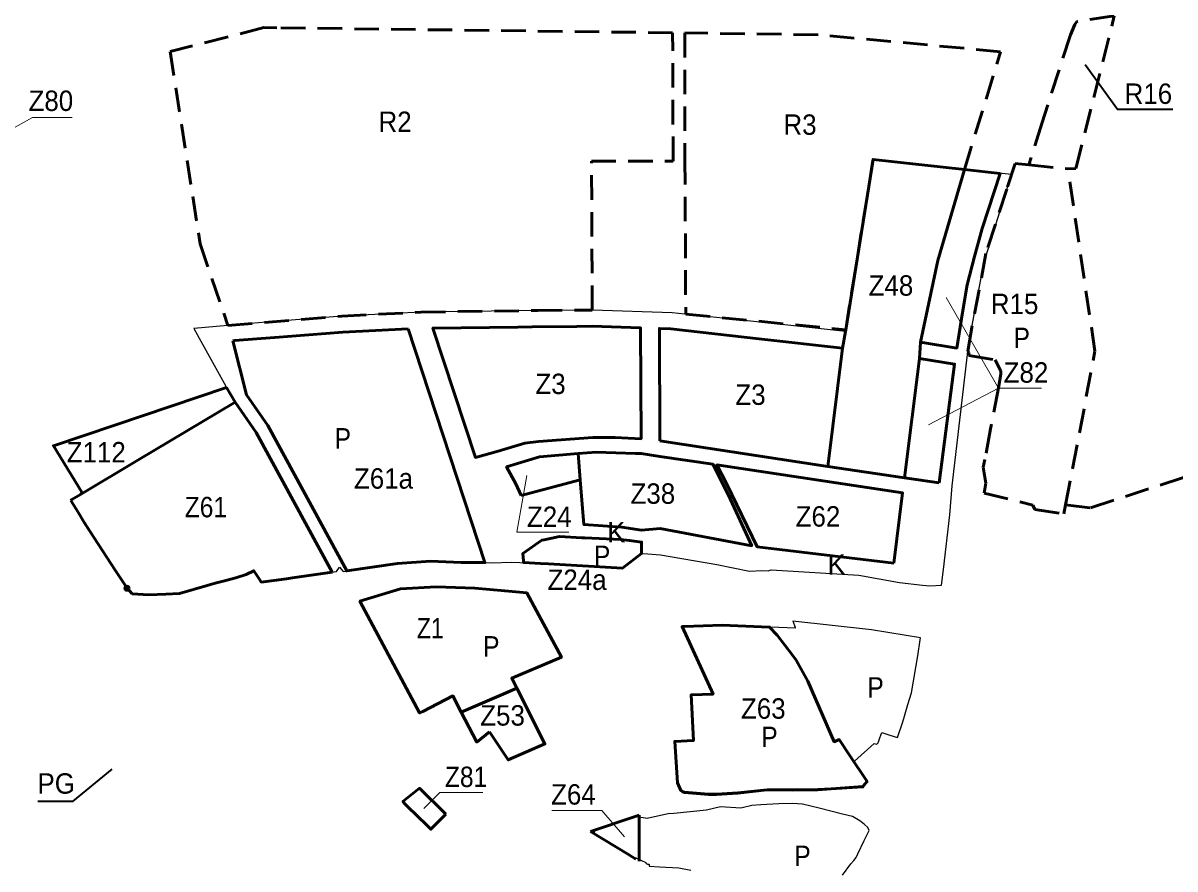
# Model space of a CAD drawing. Extents: x -650246 to -642674, y -1074280 to -1066767.
# Drawn here: x -647810 to -646455, y -1070187 to -1069193 of the extents above; entities that cross this region are included whole.
import ezdxf

# ---------------------------------------------------------------- set-up
doc = ezdxf.new("R2010")
doc.units = 0
doc.header["$LTSCALE"] = 9.6
doc.header["$PDMODE"] = 32
doc.header["$PDSIZE"] = 4.8
doc.linetypes.add('MEDIUM_DASHED', pattern=[4.5, 3, -1.5])
for name, color, linetype, lineweight in [('42', 7, 'Continuous', 25), ('44', 7, 'Continuous', 53), ('45', 7, 'Continuous', 53), ('46', 7, 'Continuous', 13), ('48', 7, 'Continuous', 13), ('60', 7, 'Continuous', 35), ('61', 7, 'MEDIUM_DASHED', 53), ('62', 7, 'Continuous', 35)]:
    doc.layers.add(name, color=color, linetype=linetype, lineweight=lineweight)

msp = doc.modelspace()

# ---------------------------------------------------------------- linework, layer by layer
at = {"layer": '42'}
for points in [[(-647235.49, -1069826.51), (-647205.603, -1069827.72), (-647191.66, -1069828.58), (-647201.106, -1069827.997), (-647191.66, -1069828.58), (-647104.741, -1069833.568), (-647082.145, -1069816.321), (-647074.72, -1069816.8), (-647060.029, -1069817.854), (-646993.81, -1069829.12), (-646993.81, -1069829.12), (-646955.45, -1069836.93), (-646940.94, -1069836.34), (-646933.39, -1069836.51), (-646929.67, -1069835.68), (-646826.63, -1069841.84), (-646778.74, -1069850.44), (-646751.8, -1069853.72), (-646743.31, -1069854.26), (-646729.54, -1069853.69), (-646727.09, -1069835.05), (-646719.79, -1069770.87), (-646716.98, -1069736.73), (-646698.96, -1069582.26), (-646698.96, -1069582.26), (-646698.4, -1069578.93), (-646693.58, -1069550.28), (-646679.13, -1069473.51), (-646647.141, -1069370.826), (-646702.425, -1069364.771), (-646809.879, -1069353.002), (-646842.103, -1069553.182), (-646842.441, -1069555.283), (-646910.029, -1069548.006), (-646986.633, -1069539.757), (-647046.325, -1069533.275), (-647140.008, -1069530.068), (-647204.293, -1069530.647), (-647341.697, -1069532.602), (-647434.969, -1069537.141), (-647523.931, -1069544.499), (-647568.792, -1069548.21), (-647608.81, -1069551.868), (-647598.735, -1069570.026), (-647573.15, -1069616.16), (-647570.37, -1069621.18), (-647570.37, -1069621.18), (-647701.61, -1069665.279), (-647774.11, -1069689.64), (-647740.74, -1069744.24), (-647742.36, -1069746.93), (-647752.32, -1069752.95), (-647753.7, -1069753.9), (-647745.84, -1069766.71), (-647687.45, -1069857.15), (-647681.51, -1069863.72), (-647661.79, -1069864.92), (-647641.78, -1069864.26), (-647625.83, -1069863.19), (-647593.07, -1069853.74), (-647572.63, -1069848.63), (-647559.47, -1069844.92), (-647547.12, -1069840.87), (-647538.34, -1069836.68), (-647531.33, -1069847.23), (-647529.5, -1069849.99), (-647492.76, -1069845.02), (-647441.19, -1069837.6), (-647437.46, -1069832.27), (-647433.32, -1069837.33), (-647369.3, -1069828.22), (-647330.46, -1069825.51), (-647294.38, -1069826.88)], [(-647294.38, -1069826.88), (-647270.09, -1069827.02), (-647258.143, -1069827.094), (-647235.49, -1069826.51)], [(-646753.995, -1069915.425), (-646811.935, -1069906.155), (-646904.446, -1069895.991), (-646901.388, -1069902.723), (-646902.06, -1069902.694), (-646901.388, -1069904.174)], [(-646901.388, -1069904.174), (-646987.56, -1069900.52), (-647032.16, -1069902.13), (-647033.853, -1069902.188)], [(-647033.853, -1069902.188), (-646998.06, -1069980.039), (-646998.716, -1069980.064)], [(-646831.912, -1070060.406), (-646808.49, -1070039.689), (-646805.65, -1070040.439), (-646803.87, -1070038.879), (-646803.43, -1070037.629), (-646801.84, -1070033.139), (-646799.45, -1070026.749), (-646790.27, -1070029.749), (-646781.39, -1070032.779), (-646774.86, -1070014.019), (-646772.96, -1070007.579), (-646768.91, -1069993.979), (-646764.81, -1069980.189), (-646757.45, -1069936.669), (-646754.36, -1069917.669), (-646753.995, -1069915.425)], [(-646998.716, -1069980.064), (-646998.06, -1069981.49), (-647023.975, -1069982.477)], [(-647023.975, -1069982.477), (-647021.27, -1070034.829), (-647021.345, -1070034.832)], [(-647021.345, -1070034.832), (-647021.27, -1070036.28), (-647043.157, -1070037.286)], [(-647043.157, -1070037.286), (-647040.12, -1070084.659), (-647036.03, -1070093.509), (-647034.17, -1070095.039), (-647031.73, -1070095.759), (-647003.49, -1070098.209), (-646993.92, -1070098.039), (-646968.89, -1070096.569), (-646934.63, -1070092.789), (-646904.97, -1070093.069)], [(-646904.97, -1070093.069), (-646874.9, -1070092.649), (-646859.29, -1070091.649), (-646821.89, -1070089.249), (-646817.427, -1070083.656), (-646831.912, -1070061.857), (-646831.305, -1070061.32), (-646831.912, -1070060.406)], [(-646845.76, -1070194.67), (-646836.06, -1070181.31), (-646832.62, -1070177.08), (-646829.87, -1070173.61), (-646827.95, -1070169.52), (-646820.51, -1070153.68), (-646814.53, -1070141.96), (-646816.06, -1070138.5), (-646820.35, -1070134.43), (-646825.4, -1070130.78), (-646834.04, -1070125.34), (-646845.78, -1070122.84), (-646873.5, -1070115.8), (-646892.87, -1070110.82), (-646904.66, -1070110.24), (-646920.68, -1070110.58), (-646941.99, -1070111.74), (-646952.66, -1070112.57), (-646965.6, -1070115.74), (-646989.24, -1070114.17), (-646989.24, -1070114.17), (-647005.97, -1070117.89), (-647044.19, -1070121.78), (-647051.14, -1070122.49), (-647070.7, -1070126.64), (-647075.81, -1070127.72), (-647090.2, -1070125.64), (-647133.96, -1070140.44), (-647136.65, -1070141.75), (-647137.99, -1070143.09), (-647137.96, -1070144.66), (-647136.09, -1070146.97), (-647132.95, -1070149.08), (-647097.63, -1070170.37), (-647077.39, -1070179.57), (-647076.83, -1070180.73), (-647075.42, -1070181.53), (-647073.42, -1070181.47), (-647073.35, -1070184.01), (-647061.2, -1070184.6), (-647038.31, -1070185.73), (-647024.2, -1070188.68)]]:
    msp.add_lwpolyline(points, dxfattribs=at)
at = {"layer": '44'}
msp.add_line((-646772.907, -1069727.177), (-646732.143, -1069733.308), dxfattribs=at)
at = {"layer": '44', "lineweight": 13}
for points in [[(-647751.811, -1069303.761), (-647798.61, -1069303.761), (-647856.005, -1069335.572)], [(-647751.811, -1069303.761), (-647798.61, -1069303.761), (-647856.005, -1069335.572)], [(-646611.673, -1069622.045), (-646662.372, -1069622.045), (-646744.747, -1069664.938), (-646662.372, -1069622.045), (-646723.996, -1069515.165)], [(-647268.839, -1070097.432), (-647319.538, -1070097.432), (-647338.315, -1070116.223)], [(-647268.839, -1070097.432), (-647319.538, -1070097.432), (-647338.315, -1070116.223)]]:
    msp.add_lwpolyline(points, dxfattribs=at)
at = {"layer": '44'}
for points in [[(-646660.526, -1069369.36), (-646702.425, -1069364.771), (-646733.74, -1069471.688), (-646754.066, -1069567.993), (-646711.442, -1069574.759), (-646704.68, -1069533.06), (-646699.07, -1069500.57), (-646690.51, -1069466.97), (-646681.5, -1069434.17)], [(-647312.485, -1070122.583), (-647329.932, -1070140.465), (-647334.81, -1070135.73), (-647357.4, -1070113.69), (-647359.8, -1070111.34), (-647362.87, -1070107.74), (-647343.454, -1070092.368)]]:
    msp.add_lwpolyline(points, close=True, dxfattribs=at)
for points in [[(-646725.82, -1069684.5), (-646714.037, -1069593.585), (-646755.269, -1069587.04), (-646772.907, -1069727.177)], [(-646732.143, -1069733.308), (-646725.82, -1069684.5), (-646725.82, -1069684.5)]]:
    msp.add_lwpolyline(points, dxfattribs=at)
at = {"layer": '45'}
for p, q in [((-647085.131, -1070123.926), (-647142.227, -1070143.236)), ((-647085.131, -1070123.926), (-647142.227, -1070143.236)), ((-647085.131, -1070177.975), (-647085.131, -1070123.926)), ((-647085.131, -1070177.975), (-647085.131, -1070123.926))]:
    msp.add_line(p, q, dxfattribs=at)
for points in [[(-646842.441, -1069555.283), (-646842.103, -1069553.182), (-646809.879, -1069353.002), (-646702.425, -1069364.771), (-646702.425, -1069364.771), (-646702.425, -1069364.771), (-646702.425, -1069364.771), (-646702.425, -1069364.771), (-646733.74, -1069471.688), (-646733.74, -1069471.688), (-646754.066, -1069567.993)], [(-646842.441, -1069555.283), (-646842.103, -1069553.182), (-646809.879, -1069353.002), (-646702.425, -1069364.771), (-646702.425, -1069364.771), (-646702.425, -1069364.771), (-646702.425, -1069364.771), (-646702.425, -1069364.771), (-646733.74, -1069471.688), (-646733.74, -1069471.688), (-646754.066, -1069567.993)], [(-647356.899, -1069552.034), (-647433.779, -1069556.106), (-647433.779, -1069556.106), (-647513.66, -1069562.249), (-647514.067, -1069562.282), (-647560.836, -1069566.036), (-647563.104, -1069566.28)], [(-647369.3, -1069828.22), (-647330.46, -1069825.51), (-647294.38, -1069826.88), (-647270.09, -1069827.02), (-647266.581, -1069827.042), (-647356.899, -1069552.034)], [(-646754.066, -1069567.993), (-646755.269, -1069587.04), (-646772.906, -1069727.176), (-646863, -1069714), (-646846, -1069575), (-646842.441, -1069555.283)], [(-646754.066, -1069567.993), (-646755.269, -1069587.04), (-646772.906, -1069727.176), (-646863, -1069714), (-646846, -1069575), (-646842.441, -1069555.283)], [(-647563.104, -1069566.28), (-647546.777, -1069629.901), (-647521.943, -1069665.763)], [(-647570.37, -1069621.18), (-647701.61, -1069665.279), (-647774.11, -1069689.64), (-647740.74, -1069744.24), (-647742.36, -1069746.93), (-647674.901, -1069706.701)], [(-647570.37, -1069621.18), (-647701.61, -1069665.279), (-647774.11, -1069689.64), (-647740.74, -1069744.24), (-647742.36, -1069746.93), (-647674.901, -1069706.701)], [(-647674.901, -1069706.701), (-647560.36, -1069638.39), (-647570.37, -1069621.18)], [(-647674.901, -1069706.701), (-647560.36, -1069638.39), (-647570.37, -1069621.18)], [(-647560.36, -1069638.39), (-647674.901, -1069706.701), (-647742.36, -1069746.93)], [(-647446.322, -1069838.338), (-647535.588, -1069674.163), (-647560.36, -1069638.39)], [(-647521.943, -1069665.763), (-647428.993, -1069836.714), (-647369.3, -1069828.22)], [(-647742.36, -1069746.93), (-647752.32, -1069752.95), (-647753.7, -1069753.9)], [(-647753.7, -1069753.9), (-647751.66, -1069757.12), (-647745.84, -1069766.71), (-647737.17, -1069780.85), (-647700.58, -1069837.2), (-647687.45, -1069857.15), (-647681.51, -1069863.72)], [(-647641.78, -1069864.26), (-647625.83, -1069863.19), (-647593.07, -1069853.74), (-647583.62, -1069851.13), (-647572.63, -1069848.63), (-647559.47, -1069844.92), (-647547.12, -1069840.87), (-647538.34, -1069836.68), (-647536.82, -1069838.87), (-647531.33, -1069847.23), (-647529.5, -1069849.99), (-647500.03, -1069846.28), (-647492.76, -1069845.02), (-647446.322, -1069838.338)], [(-647681.51, -1069863.72), (-647661.79, -1069864.92), (-647641.78, -1069864.26)], [(-647142.227, -1070143.236), (-647097.63, -1070170.37), (-647088.916, -1070175.672)], [(-647142.227, -1070143.236), (-647097.63, -1070170.37), (-647088.916, -1070175.672)]]:
    msp.add_lwpolyline(points, dxfattribs=at)
for points in [[(-647251.002, -1069695.852), (-647219.628, -1069686.746), (-647203.374, -1069684.716), (-647139.649, -1069679.961), (-647113.255, -1069679.966), (-647082.761, -1069681.399), (-647083.356, -1069551.018), (-647140.247, -1069549.071), (-647158.572, -1069549.252), (-647211.05, -1069549.77), (-647227.623, -1069550.23), (-647327.682, -1069551.263), (-647277.71, -1069703.421)], [(-647251.002, -1069695.852), (-647219.628, -1069686.746), (-647203.374, -1069684.716), (-647139.649, -1069679.961), (-647113.255, -1069679.966), (-647082.761, -1069681.399), (-647083.356, -1069551.018), (-647140.247, -1069549.071), (-647158.572, -1069549.252), (-647211.05, -1069549.77), (-647227.623, -1069550.23), (-647327.682, -1069551.263), (-647277.71, -1069703.421)], [(-647060.7, -1069683.894), (-647061.304, -1069551.773), (-647047.648, -1069552.245), (-646944.168, -1069563.743), (-646846, -1069575), (-646863, -1069714)], [(-647060.7, -1069683.894), (-647061.304, -1069551.773), (-647047.648, -1069552.245), (-646944.168, -1069563.743), (-646846, -1069575), (-646863, -1069714)], [(-647223.66, -1069748.26), (-647154.33, -1069729.69), (-647156.782, -1069698.901), (-647202.181, -1069702.678), (-647240.994, -1069714.513), (-647230.16, -1069734.42)], [(-647223.66, -1069748.26), (-647154.33, -1069729.69), (-647156.782, -1069698.901), (-647202.181, -1069702.678), (-647240.994, -1069714.513), (-647230.16, -1069734.42)], [(-647060.617, -1069702.116), (-647082.682, -1069698.791), (-647089.456, -1069698.579), (-647135.585, -1069697.137), (-647156.782, -1069698.901), (-647154.33, -1069729.69), (-647150.138, -1069782.334), (-647105.334, -1069785.168), (-647082.271, -1069788.81), (-647060.23, -1069786.932), (-646952.56, -1069807.13), (-646980.4, -1069746.98), (-646998.56, -1069711.443)], [(-646785.437, -1069827.534), (-646775.286, -1069745.022), (-646993.771, -1069712.163), (-646981.92, -1069734.86), (-646946.369, -1069808.291)], [(-646785.437, -1069827.534), (-646775.286, -1069745.022), (-646993.771, -1069712.163), (-646981.92, -1069734.86), (-646946.369, -1069808.291)], [(-647196.616, -1069800.068), (-647199.65, -1069800.69), (-647221.87, -1069816.21), (-647221.28, -1069824.74), (-647221.14, -1069826.761), (-647201.106, -1069827.997), (-647191.66, -1069828.58), (-647104.741, -1069833.568), (-647082.145, -1069816.321), (-647082.206, -1069802.916), (-647096.39, -1069801.15), (-647107.04, -1069799.84), (-647148.9, -1069797.88), (-647152.39, -1069797.7), (-647178.73, -1069796.4)], [(-647365.866, -1069857.774), (-647413.461, -1069872.442), (-647343.28, -1070003.81), (-647339.69, -1070001.95), (-647330.5, -1069997.19), (-647304.05, -1069983.79), (-647294.257, -1070002.745), (-647242.254, -1069980.33), (-647229.096, -1069974.658), (-647235, -1069963), (-647176.499, -1069938.333), (-647205.781, -1069883.796), (-647217.177, -1069862.57), (-647243.231, -1069860.34), (-647278.525, -1069857.002), (-647323.794, -1069855.468)], [(-647365.866, -1069857.774), (-647413.461, -1069872.442), (-647343.28, -1070003.81), (-647339.69, -1070001.95), (-647330.5, -1069997.19), (-647304.05, -1069983.79), (-647294.257, -1070002.745), (-647242.254, -1069980.33), (-647229.096, -1069974.658), (-647235, -1069963), (-647176.499, -1069938.333), (-647205.781, -1069883.796), (-647217.177, -1069862.57), (-647243.231, -1069860.34), (-647278.525, -1069857.002), (-647323.794, -1069855.468)], [(-647032.16, -1069902.13), (-647034.51, -1069902.21), (-646998.06, -1069981.49), (-647024.05, -1069982.48), (-647021.27, -1070036.28), (-647043.25, -1070037.29), (-647040.12, -1070086.11), (-647036.03, -1070094.96), (-647034.17, -1070096.49), (-647031.73, -1070097.21), (-647003.49, -1070099.66), (-646993.92, -1070099.49), (-646968.89, -1070098.02), (-646934.63, -1070094.24), (-646904.97, -1070094.52), (-646874.9, -1070094.1), (-646859.29, -1070093.1), (-646821.89, -1070090.7), (-646817.15, -1070084.76), (-646816.9, -1070084.45), (-646837.65, -1070053.22), (-646849.79, -1070035.17), (-646855.62, -1070037.66), (-646886.85, -1069966.26), (-646900.26, -1069941.64), (-646904.72, -1069935.84), (-646922.79, -1069912.31), (-646931.67, -1069902.89), (-646987.56, -1069900.52)], [(-647261.27, -1070026.12), (-647238.99, -1070059.05), (-647195.933, -1070040.107), (-647229.096, -1069974.658), (-647294.257, -1070002.745), (-647276, -1070038.08)], [(-647261.27, -1070026.12), (-647238.99, -1070059.05), (-647195.933, -1070040.107), (-647229.096, -1069974.658), (-647294.257, -1070002.745), (-647276, -1070038.08)]]:
    msp.add_lwpolyline(points, close=True, dxfattribs=at)
msp.add_point((-647687.45, -1069857.15), dxfattribs=at)
at = {"layer": '46'}
for points in [[(-647167.693, -1069791.112), (-647229.126, -1069791.112), (-647217.012, -1069724.439)], [(-647167.693, -1069791.112), (-647229.126, -1069791.112), (-647217.012, -1069724.439)], [(-647187.627, -1070118.571), (-647128.949, -1070118.571), (-647102.191, -1070149.577)], [(-647187.627, -1070118.571), (-647128.949, -1070118.571), (-647102.191, -1070149.577)]]:
    msp.add_lwpolyline(points, dxfattribs=at)
at = {"layer": '60'}
msp.add_lwpolyline([(-647792.254, -1070107.298), (-647750.945, -1070107.298), (-647704.94, -1070069.715)], dxfattribs=at)
msp.add_lwpolyline([(-647792.254, -1070107.298), (-647750.945, -1070107.298), (-647704.94, -1070069.715)], dxfattribs=at)
at = {"layer": '61'}
msp.add_line((-646626.774, -1069359.349), (-646642.89, -1069357.68), dxfattribs=at)
for points in [[(-646583.457, -1069759.191), (-646554.262, -1069762.602), (-646321.973, -1069686.855), (-646209.9, -1069538.5), (-646146.8, -1069506.6), (-646148.5, -1069503), (-646028.16, -1069441.58), (-646023.96, -1069440.34), (-646075.49, -1069318.19), (-646025.14, -1069285.394), (-646153.307, -1069059.947)], [(-646642.89, -1069357.68), (-646652.72, -1069388.08), (-646677.18, -1069463.79), (-646693.58, -1069550.28), (-646698.4, -1069578.93), (-646697.31, -1069579.97), (-646697.31, -1069583.47), (-646666.36, -1069588.57), (-646659.83, -1069601.8), (-646659.52, -1069605.53), (-646662.57, -1069621.66), (-646671.69, -1069669.92), (-646678.52, -1069705.63), (-646680.28, -1069714.83), (-646677.36, -1069733.65), (-646679.46, -1069745.37), (-646622, -1069759.34), (-646619.49, -1069764.46), (-646585.51, -1069769.57), (-646583.457, -1069759.191), (-646548.91, -1069578.56), (-646580.797, -1069364.111)]]:
    msp.add_lwpolyline(points, dxfattribs=at)
for points in [[(-646572.586, -1069194.485), (-646577.878, -1069206.485), (-646611.107, -1069309.68), (-646626.774, -1069359.349), (-646580.797, -1069364.111), (-646571.479, -1069363.822), (-646526.31, -1069184.381), (-646570.296, -1069190.776)], [(-647045.7, -1069204.106), (-647511.107, -1069198.223), (-647526.615, -1069198.093), (-647636.743, -1069226.014), (-647601.568, -1069452.14), (-647568.792, -1069548.21), (-647434.969, -1069537.141), (-647341.697, -1069532.602), (-647204.293, -1069530.647), (-647140.334, -1069530.057), (-647141.134, -1069354.872), (-647045.123, -1069355.003)], [(-647031.152, -1069204.288), (-647031.152, -1069353.712), (-647030.324, -1069535.053), (-646842.103, -1069553.182), (-646809.879, -1069353.002), (-646702.425, -1069364.771), (-646659.946, -1069226.375), (-646874.542, -1069206.4)]]:
    msp.add_lwpolyline(points, close=True, dxfattribs=at)
at = {"layer": '62'}
msp.add_lwpolyline([(-646457.55, -1069294.294), (-646522.377, -1069294.294), (-646560.609, -1069241.94)], dxfattribs=at)
at = {"layer": '62', "lineweight": 13}
msp.add_lwpolyline([(-646457.55, -1069294.294), (-646522.377, -1069294.294), (-646560.609, -1069241.94)], dxfattribs=at)

# ---------------------------------------------------------------- texts
at = {"layer": '44'}
for s, width, p in [('Z80', 0.95, (-647803.311, -1069296.044)), ('Z80', 0.95, (-647803.311, -1069296.044)), ('Z82', 0.95, (-646656.364, -1069615.463)), ('Z81', 0.9, (-647313.531, -1070090.851)), ('Z81', 0.9, (-647313.531, -1070090.851))]:
    msp.add_text(s, height=24, dxfattribs=dict(at, width=width)).set_placement(p)
at = {"layer": '46'}
for s, width, p in [('Z48', 0.95, (-646815.179, -1069513.185)), ('Z48', 0.95, (-646815.179, -1069513.185)), ('Z3', 0.95, (-647207.094, -1069628.872)), ('Z3', 0.95, (-647207.094, -1069628.872)), ('Z3', 0.95, (-646971.871, -1069641.589)), ('Z3', 0.95, (-646971.871, -1069641.589)), ('Z112', 0.95, (-647758.383, -1069709.22)), ('Z112', 0.95, (-647758.383, -1069709.22)), ('Z61a', 0.95, (-647420.53, -1069740.066)), ('Z38', 0.95, (-647095.223, -1069757.854)), ('Z38', 0.95, (-647095.223, -1069757.854)), ('Z61', 0.9, (-647619.576, -1069773.738)), ('Z24', 0.95, (-647217.069, -1069785.057)), ('Z24', 0.95, (-647217.069, -1069785.057)), ('Z62', 0.95, (-646900.991, -1069784.684)), ('Z62', 0.95, (-646900.991, -1069784.684)), ('Z24a', 0.95, (-647192.847, -1069859.131)), ('Z1', 0.85, (-647346.649, -1069916.072)), ('Z1', 0.85, (-647346.649, -1069916.072)), ('Z63', 0.95, (-646965.327, -1070010.57)), ('Z53', 0.95, (-647272.017, -1070018.639)), ('Z53', 0.95, (-647272.017, -1070018.639)), ('Z64', 0.95, (-647188.663, -1070111.521)), ('Z64', 0.95, (-647188.663, -1070111.521))]:
    msp.add_text(s, height=24, dxfattribs=dict(at, width=width)).set_placement(p)
at = {"layer": '48'}
for p in [(-647122.713, -1069803.226), (-646863.536, -1069841.154)]:
    msp.add_text('K', height=24, dxfattribs=at).set_placement(p)
at = {"layer": '60'}
for s, width, p in [('P', 0.9, (-646644.717, -1069574.793)), ('P', 0.9, (-646644.717, -1069574.793)), ('P', 0.9, (-647443.274, -1069692.913)), ('P', 0.9, (-647443.274, -1069692.913)), ('P', 0.9, (-647138.27, -1069830.996)), ('P', 0.9, (-647138.27, -1069830.996)), ('P', 0.9, (-647268.59, -1069937.47)), ('P', 0.9, (-647268.59, -1069937.47)), ('P', 0.9, (-646816.629, -1069985.717)), ('P', 0.9, (-646816.629, -1069985.717)), ('P', 0.9, (-646941.403, -1070043.945)), ('P', 0.9, (-646941.403, -1070043.945)), ('PG', 0.95, (-647792.805, -1070098.685)), ('PG', 0.95, (-647792.805, -1070098.685)), ('P', 0.9, (-646902.585, -1070183.692)), ('P', 0.9, (-646902.585, -1070183.692))]:
    msp.add_text(s, height=24, dxfattribs=dict(at, width=width)).set_placement(p)
at = {"layer": '62', "width": 0.95}
for s, p in [('R16', (-646514.063, -1069287.733)), ('R2', (-647391.654, -1069320.724)), ('R2', (-647391.654, -1069320.724)), ('R3', (-646915.354, -1069324.087)), ('R3', (-646915.354, -1069324.087)), ('R15', (-646671.455, -1069534.875)), ('R15', (-646671.455, -1069534.875))]:
    msp.add_text(s, height=24, dxfattribs=at).set_placement(p)

doc.saveas('drawing.dxf')
